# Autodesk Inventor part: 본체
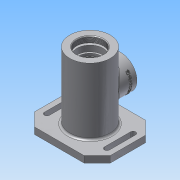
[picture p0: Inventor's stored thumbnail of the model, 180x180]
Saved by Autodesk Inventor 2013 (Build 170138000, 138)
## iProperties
Created: 2017-10
Part Number: 본체
Material: 알루미늄 6061
Document SubType Name: Modeling
Designer: Administrator
Density: 2.71 g/cm^3
Mass: 740.7 g
Surface Area: 652.733 cm^2
Volume: 273.321 cm^3
Author: Administrator
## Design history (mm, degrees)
sketch "스케치1"
  geometry: C1 r 31 at (0, 0); 1 further point
  constraints: 1 centre point, 1 coincident
  dimensions: "d0" = 62 diameter of C1
extrude "돌출1" new body sketch "스케치1" distance "d2" = 102; taper "d3" = 0 deg
node "작업 평면1"
sketch "스케치2"
  geometry: L1 (31, 102)-(-31, 102) reference; C1 r 25 at (0, 46); 1 further point
  constraints: 1 centre point, 1 vertical alignment
  dimensions: "d5" = 50 diameter of C1; "d7" = 56 distance from line of L1 C1.centre
extrude "돌출2" join sketch "스케치2" stored distance "d8" = 102; taper "d9" = 0 deg
sketch "스케치3"
  geometry: L1 (-58, -47)-(58, -47); L2 (58, -47)-(58, 47); L3 (58, 47)-(-58, 47); L4 (-58, 47)-(-58, -47); L5 (-58, -47)-(58, 47); L6 (58, -47)-(-58, 47); C1 r 31 at (0, 0) reference
  constraints: 12 end point, 2 midpoint, 2 parallel, 1 horizontal, 1 perpendicular
  dimensions: "d10" = 116 distance of L3.end L2.end; "d11" = 94 distance of L2.end L1.end
extrude "돌출3" join sketch "스케치3" distance "d12" = 10; taper "d13" = 0 deg
chamfer "모따기1" distance "d14" = 20; stored, may be unused: second distance "d15" = 2, angle "d16" = 45 deg
sketch "스케치4"
  geometry: C1 r 35 at (0, 0); 1 further point
  constraints: 1 centre point, 1 coincident
  dimensions: "d17" = 70 diameter of C1
extrude "돌출4" join sketch "스케치4" distance "d19" = 3; taper "d20" = 0 deg
sketch "스케치5"
  geometry: L1 (58, -27)-(58, 27) reference; L2 (42, -20)-(42, 20); L3 (50, 20)-(50, -20); C1 r 35 at (0, 0) reference; A1 r 4 centre (46, 20) between (50, 20) and (42, 20); A2 r 4 centre (46, -20) between (42, -20) and (50, -20); 1 further point
  constraints: 4 end point, 4 point on circle, 3 parallel, 2 centre point, 2 tangent, 1 equal radius, 1 horizontal alignment, 1 midpoint
  dimensions: "d21" = 40 distance of L2.start L2.end; "d22" = 4 radius of A1; "d23" = 46 horizontal distance of C1.centre A2.centre
extrude "돌출5" cut sketch "스케치5" stored distance "d24" = 3; taper "d25" = 0 deg
node "작업 평면2"
sketch "스케치6"
  geometry: L1 (31, 102)-(-31, 102) reference; L2 (47, 71)-(47, 21) reference; 2 further points
  constraints: 1 other
  dimensions: "d27" = 56 distance from line of L1 point (37, 46); "d28" = 10 distance from line of L2 point (37, 46)
feature "엠보싱1" sketch "스케치6" dims "d0" = 62, "d29" = 0.5, "d30" = 0
sketch "스케치7"
  geometry: C1 r 31 at (0, 0) reference
hole "구멍1" sketch "스케치7" at (0, 0) diameter "d31" = 40.376; stored, may be unused: countersink angle "d35" = 90 deg, drill point angle "d37" = 0 deg; dims "d32" = 6, "d33" = 4, "d34" = 2, "d36" = 9
sketch "스케치8"
  geometry: C1 r 20.188 at (0, 0) reference; C2 r 24 at (0, 0)
  constraints: 1 centre point, 1 coincident
  dimensions: "d38" = 48 diameter of C2
extrude "돌출6" cut sketch "스케치8" distance "d40" = 3; taper "d41" = 0 deg
sketch "스케치9"
  geometry: C1 r 24 at (0, 0) reference; C2 r 20 at (0, 0)
  constraints: 1 centre point, 1 coincident
  dimensions: "d43" = 40 diameter of C2
extrude "돌출7" cut sketch "스케치9" distance "d45" = 9; taper "d46" = 0 deg
sketch "스케치10"
  geometry: C1 r 20 at (0, 0) reference; C2 r 17.5 at (0, 0)
  constraints: 1 centre point, 1 coincident
  dimensions: "d47" = 35 diameter of C2
extrude "돌출8" cut sketch "스케치10" distance "d49" = 3.25; taper "d50" = 0 deg
sketch "스케치11"
  geometry: C1 r 17.5 at (0, 0) reference; C2 r 18.5 at (0, 0)
  constraints: 1 centre point, 1 coincident
  dimensions: "d51" = 37 diameter of C2
extrude "돌출9" cut sketch "스케치11" distance "d53" = 1.75; taper "d54" = 0 deg
sketch "스케치12"
  geometry: C1 r 18.5 at (0, 0) reference; C2 r 17.5 at (0, 0)
  constraints: 1 centre point, 1 coincident
  dimensions: "d55" = 35 diameter of C2
extrude "돌출10" cut sketch "스케치12" distance "d57" = 11; taper "d58" = 0 deg
sketch "스케치13"
  geometry: C1 r 17.5 at (0, 0) reference; C2 r 26 at (0, 0)
  constraints: 1 centre point, 1 coincident
  dimensions: "d59" = 52 diameter of C2
extrude "돌출11" cut sketch "스케치13" distance "d61" = 38; taper "d62" = 0 deg
sketch "스케치14"
  geometry: C1 r 26 at (0, 0) reference; C2 r 17.5 at (0, 0)
  constraints: 1 centre point, 1 coincident
  dimensions: "d63" = 35 diameter of C2
extrude "돌출12" cut sketch "스케치14" distance "d65" = 11; taper "d66" = 0 deg
sketch "스케치15"
  geometry: C1 r 17.5 at (0, 0) reference; C2 r 16.5 at (0, 0)
  constraints: 1 centre point, 1 coincident
  dimensions: "d67" = 33 diameter of C2
extrude "돌출13" cut sketch "스케치15" distance "d69" = 5; taper "d70" = 0 deg
sketch "스케치16"
  geometry: C1 r 16.5 at (0, 0) reference; C2 r 10 at (0, 0)
  constraints: 1 centre point, 1 coincident
  dimensions: "d71" = 20 diameter of C2
extrude "돌출14" cut sketch "스케치16" distance "d73" = 2.7; taper "d74" = 0 deg
sketch "스케치17"
  geometry: C1 r 10 at (0, 0) reference; C2 r 12.5 at (0, 0)
  constraints: 1 centre point, 1 coincident
  dimensions: "d75" = 25 diameter of C2
extrude "돌출15" cut sketch "스케치17" distance "d77" = 7.3; taper "d78" = 0 deg
sketch "스케치18"
  geometry: L1 (-12.5, 1)-(12.5, 1) reference; L2 (-35, -13)-(35, -13) reference; L3 (0, 1)-(16, 1); L4 (0, 1)-(0, -13); L5 (0, -13)-(22, -13); L6 (22, -13)-(16, 1); 1 further point
  constraints: 8 end point, 2 midpoint, 2 point on line
  dimensions: "d79" = 16 distance of L3.start L3.end; "d80" = 14 distance of L3.start L4.end; "d82" = 22 distance of L4.end L5.end
revolve "회전1" sketch "스케치18" stored, may be unused: angle "d83" = 90 deg
sketch "스케치19"
  geometry: C1 r 25 at (0, 0) reference; C2 r 16 at (0, 0); 1 further point
  constraints: 1 centre point, 1 coincident
  dimensions: "d84" = 32 diameter of C2
extrude "돌출16" cut sketch "스케치19" distance "d86" = 47; taper "d87" = 0 deg
sketch "스케치20"
  geometry: L1 (0, 0)-(-20.5, 0); L2 (0, 0)-(20.5, 0); C1 r 25 at (0, 0) reference; 1 further point
  constraints: 4 end point, 1 collinear, 1 horizontal
  dimensions: "d89" = 20.5 distance of L1.start L1.end; "d90" = 20.5 distance of L1.start L2.end
hole "구멍2" sketch "스케치20" at (-20.5, 0), (20.5, 0) diameter "d91" = 2.459; stored, may be unused: countersink angle "d95" = 90 deg, drill point angle "d97" = 118 deg; dims "d92" = 6, "d93" = 4, "d94" = 2, "d96" = 8
fillet "모깎기1" dims "d98" = 3
chamfer "모따기2" distance "d99" = 1; stored, may be unused: second distance "d100" = 2, angle "d101" = 45 deg
fillet "모깎기2" dims "d102" = 3
chamfer "모따기3" distance "d103" = 1; stored, may be unused: second distance "d104" = 2, angle "d105" = 45 deg
fillet "모깎기3" dims "d106" = 3
chamfer "모따기4" distance "d107" = 0.7; stored, may be unused: second distance "d108" = 2, angle "d109" = 30 deg
fillet "모깎기4" dims "d110" = 0.3
fillet "모깎기5" dims "d111" = 3
fillet "모깎기6" dims "d112" = 0.3
chamfer "모따기5" distance "d113" = 1; stored, may be unused: second distance "d114" = 2, angle "d115" = 30 deg
node "솔리드1"
mirror "대칭1"
other parameters: "d4" = 47
